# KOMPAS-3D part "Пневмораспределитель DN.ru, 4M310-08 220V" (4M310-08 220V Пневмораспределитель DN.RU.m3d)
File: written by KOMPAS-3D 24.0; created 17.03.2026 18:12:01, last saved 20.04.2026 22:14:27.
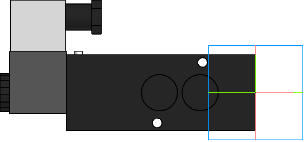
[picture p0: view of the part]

Document properties: Автор: R2D2; Полное имя файла: E:\Работа\Зайцев\Аксессуары для пневмоприводов\Пневмораспределители DN.ru\4М310-08 NAMUR Пневмораспределитель DN.RU\4M310-08 220V NAMUR Пневмораспределитель DN.RU\4M310-08 220V Пневмораспределитель DN.RU.m3d

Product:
- Part/product: Пневмораспределитель DN.ru  | designation 4M310-08 220V
    Масса: 0.35
    Раздел спецификации: Прочие изделия
    Примечание: D290-00331

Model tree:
1. Операция без истории:1

Expressions: 4M310-08 220V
